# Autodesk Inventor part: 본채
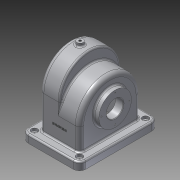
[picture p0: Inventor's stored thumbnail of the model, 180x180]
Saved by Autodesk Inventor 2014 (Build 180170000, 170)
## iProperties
Created: 2017-11
Part Number: 본채
Material: 알루미늄 6061
Document SubType Name: Modeling
Designer: user
Density: 2.71 g/cm^3
Appearance: 알루미늄 - 평지
Mass: 1015.85 g
Surface Area: 1181.14 cm^2
Volume: 374.854 cm^3
Author: user
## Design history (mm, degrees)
sketch "스케치2"
  geometry: L1 (-55, 75)-(55, 75); L2 (55, 75)-(55, -75); L3 (55, -75)-(-55, -75); L4 (-55, -75)-(-55, 75); L5 (-55, 75)-(55, -75); L6 (55, 75)-(-55, -75); 1 further point
  constraints: 12 end point, 2 midpoint, 2 parallel, 1 horizontal, 1 perpendicular
  dimensions: "d5" = 110 distance of L1.start L1.end; "d6" = 150 distance of L1.end L2.end
extrude "돌출1" new body sketch "스케치2" distance "d7" = 15; taper "d8" = 0 deg
sketch "스케치3"
  geometry: L1 (-75, 15)-(75, 15) reference; L2 (-58, 80)-(-58, 15); L3 (58, 80)-(58, 15); L4 (-58, 15)-(58, 15); L5 (75, 0)-(-75, 0) reference; A1 r 58 centre (0, 80) between (58, 80) and (-58, 80); 3 further points
  constraints: 6 end point, 3 perpendicular, 3 point on circle, 2 horizontal alignment, 2 point on line, 2 tangent, 2 vertical alignment, 1 centre point, 1 midpoint
  dimensions: "d9" = 58 radius of A1; "d11" = 80 distance from line of L5 L2.start
extrude "돌출2" new body sketch "스케치3" distance "d12" = 38; taper "d13" = 0 deg
sketch "스케치4"
  geometry: L1 (-80, -58)-(-15, -58) reference; L2 (-15, 58)-(-80, 58) reference; L3 (0, 75)-(0, -75) reference; L4 (-57, -58)-(-15, -58); L5 (-57, 58)-(-15, 58); L6 (-15, 58)-(-15, -58); A1 r 58 centre (-80, 0) between (-80, 58) and (-80, -58) reference; A2 r 58 centre (-57, 0) between (-57, 58) and (-57, -58)
  constraints: 6 end point, 2 point on circle, 2 vertical alignment, 1 centre point, 1 perpendicular, 1 point on line, 1 tangent
  dimensions: "d18" = 57 distance from line of L3 A2.centre; "d19" = 58 radius of A2
extrude "돌출3" join sketch "스케치4" distance "d20" = 38; taper "d21" = 0 deg
feature "쉘1" dims "d22" = 5
sketch "스케치6"
  geometry: L1 (-33, 53)-(33, 53) reference; L2 (-33, -53)-(-33, 53) reference; L3 (33, 53)-(33, -53) reference; L4 (33, -53)-(-33, -53) reference; 1 further point
extrude "돌출4" cut sketch "스케치6" stored distance "d23" = 38; taper "d24" = 0 deg
feature "결합1"
  node "솔리드1"
sketch "스케치7"
  geometry: L1 (0, -75)-(0, 75) reference; C1 r 37.5 at (65, 0); 1 further point
  constraints: 1 centre point, 1 horizontal alignment, 1 midpoint
  dimensions: "d27" = 75 diameter of C1; "d28" = 65 distance from line of L1 C1.centre
extrude "돌출5" join sketch "스케치7" distance "d29" = 9; taper "d30" = 0 deg
sketch "스케치8"
  geometry: L1 (0, 75)-(0, -75) reference; C1 r 31 at (-65, 0); 1 further point
  constraints: 1 centre point, 1 horizontal alignment, 1 midpoint
  dimensions: "d31" = 62 diameter of C1; "d32" = 65 distance from line of L1 C1.centre
extrude "돌출6" join sketch "스케치8" distance "d33" = 10; taper "d34" = 0 deg
sketch "스케치9"
  geometry: C1 r 37.5 at (0, 0) reference; 1 further point
hole "구멍1" sketch "스케치9" at (0, 0) diameter "d35" = 32; stored, may be unused: countersink angle "d39" = 90 deg, drill point angle "d41" = 118 deg; dims "d36" = 6, "d37" = 4, "d38" = 2, "d40" = 8
sketch "스케치10" dims "d42" = 58
  geometry: C1 r 16 at (0, 0) reference; C2 r 37.5 at (0, 0) reference; 3 further points
  constraints: 2 horizontal alignment, 1 coincident, 2 other
hole "구멍2" sketch "스케치10" at (29, 0) diameter "d43" = 2.459; stored, may be unused: countersink angle "d47" = 90 deg, drill point angle "d49" = 118 deg; dims "d44" = 6, "d45" = 4, "d46" = 2, "d48" = 8
sketch "스케치11" dims "d53" = 52
  geometry: C1 r 16 at (0, 0) reference; C2 r 31 at (0, 0) reference; 3 further points
  constraints: 2 vertical alignment, 1 coincident, 2 other
hole "구멍3" sketch "스케치11" at (0, 26) diameter "d54" = 2.459; stored, may be unused: countersink angle "d58" = 90 deg, drill point angle "d60" = 118 deg; dims "d55" = 6, "d56" = 4, "d57" = 2, "d59" = 8
node "작업 평면1"
sketch "스케치12"
  geometry: L1 (93, -133)-(93, -17) reference; C1 r 6 at (74, -75); 1 further point
  constraints: 1 centre point, 1 horizontal alignment
  dimensions: "d65" = 12 diameter of C1; "d66" = 19 distance from line of L1 C1.centre
extrude "돌출7" join sketch "스케치12" stored distance "d67" = 9; taper "d68" = 0 deg
sketch "스케치13"
  geometry: C1 r 6 at (0, 0) reference; 1 further point
hole "구멍4" sketch "스케치13" at (0, 0) diameter "d69" = 4.459; stored, may be unused: countersink angle "d73" = 90 deg, drill point angle "d75" = 118 deg; dims "d70" = 20, "d71" = 4, "d72" = 2, "d74" = 8
fillet "모깎기1" dims "d76" = 12
sketch "스케치14"
  geometry: A1 r 12 centre (86, -12) between (98, -12) and (86, 0) reference; A2 r 12 centre (0, -12) between (0, 0) and (-12, -12) reference; A3 r 12 centre (0, -138) between (-12, -138) and (0, -150) reference; A4 r 12 centre (86, -138) between (86, -150) and (98, -138) reference; 1 further point
hole "구멍5" sketch "스케치14" at (0, -12), (0, -138), (86, -12), (86, -138) diameter "d77" = 5; stored, may be unused: countersink angle "d81" = 90 deg, drill point angle "d83" = 118 deg; dims "d78" = 6, "d79" = 12, "d80" = 5, "d82" = 8
fillet "모깎기2" dims "d84" = 3
chamfer "모따기1" distance "d85" = 1; stored, may be unused: second distance "d86" = 2, angle "d87" = 45 deg
chamfer "모따기2" distance "d88" = 1; stored, may be unused: second distance "d89" = 2, angle "d90" = 45 deg
fillet "모깎기3" dims "d91" = 8
fillet "모깎기4" dims "d92" = 3
fillet "모깎기5" dims "d93" = 3
fillet "모깎기6" dims "d94" = 3
sketch "스케치15"
  geometry: L1 (73, -18)-(-13, -18) reference; L2 (68, 0)-(68, 39) reference; 2 further points
  constraints: 1 other
  dimensions: "d95" = 40 distance from line of L1 point (30, 22); "d96" = 38 distance from line of L2 point (30, 22)
feature "엠보싱1" sketch "스케치15" dims "d5" = 110, "d6" = 150, "d97" = 0.5, "d98" = 0
fillet "모깎기7" dims "d99" = 3
pattern_circular "원형 패턴1" dims angle "d51" = 360 deg
pattern_circular "원형 패턴2" dims angle "d62" = 360 deg
node "솔리드2"
other parameters: "d64" = -144
